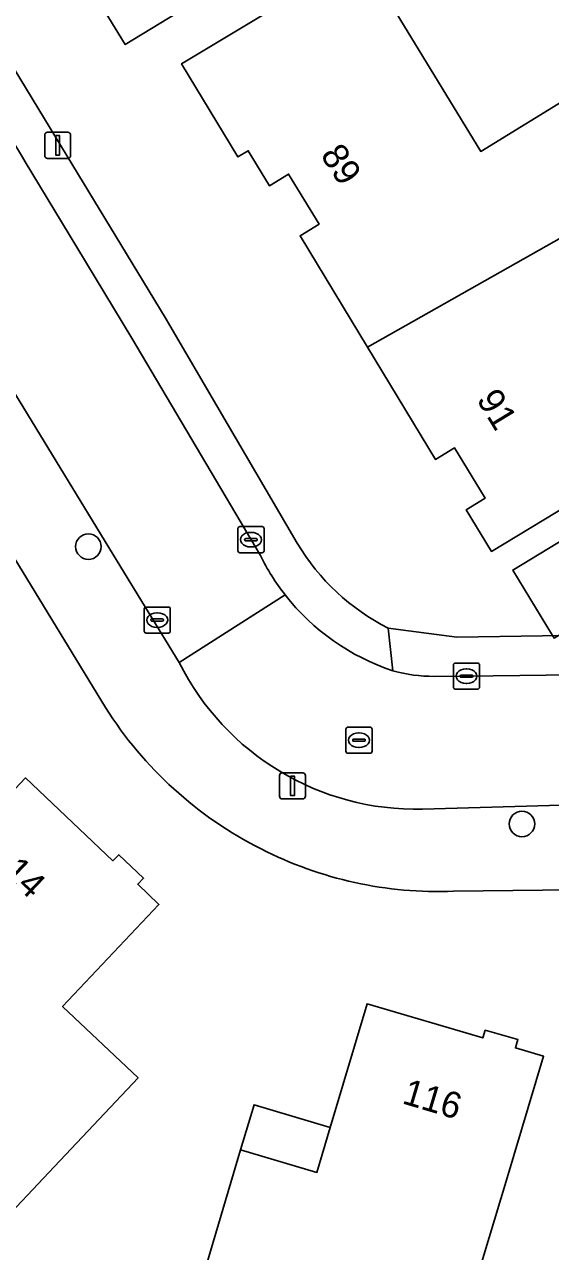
# Model space of a CAD drawing. Extents: x 157767 to 159172, y 387839 to 389425.
# Drawn here: x 158070.43 to 158090.6, y 388608.77 to 388655.84 of the extents above; entities that cross this region are included whole.
import ezdxf

# ---------------------------------------------------------------- set-up
doc = ezdxf.new("R2010")
doc.units = 0
for name, color, linetype in [('IMGEO_Boom', 7, 'Continuous'), ('IMGEO_Erf', 7, 'Continuous'), ('IMGEO_Kolk', 7, 'Continuous'), ('IMGEO_Lichtmast', 7, 'Continuous'), ('IMGEO_Muur', 7, 'Continuous'), ('IMGEO_Pand', 7, 'Continuous'), ('IMGEO_Pand_nummerreeks', 7, 'Continuous'), ('IMGEO_Pand_overbouw', 7, 'Continuous'), ('IMGEO_Rijbaan_lokaal_open', 7, 'Continuous'), ('IMGEO_Rioolput', 7, 'Continuous'), ('IMGEO_Voetpad_open', 7, 'Continuous')]:
    doc.layers.add(name, color=color, linetype=linetype)

msp = doc.modelspace()

# ---------------------------------------------------------------- linework, layer by layer
at = {"layer": 'IMGEO_Boom'}
for centre in [(158072.879, 388635.811), (158089.511, 388625.171)]:
    msp.add_circle(centre, 0.489, dxfattribs=at)
at = {"layer": 'IMGEO_Erf'}
for points in [[(158084.381, 388632.682), (158087.009, 388632.342), (158090.303, 388632.39), (158090.684, 388632.396), (158089.16, 388634.912), (158092.905, 388637.179), (158094.487, 388634.565), (158090.907, 388632.399), (158106.724, 388632.63), (158109.87, 388633.38), (158113.99, 388634.449), (158158.26, 388653.682), (158159.32, 388658.046), (158157.478, 388662.318), (158148.912, 388682.181)], [(158068.943, 388680.157), (158069.57, 388679.146), (158073.821, 388681.779), (158076.455, 388677.529), (158077.139, 388676.424), (158076.034, 388675.74), (158077.06, 388674.085), (158076.816, 388673.284), (158073.526, 388671.246), (158069.275, 388668.613), (158067.496, 388671.486), (158066.81, 388671.062), (158064.973, 388674.028), (158063.613, 388673.186), (158061.971, 388675.839), (158058.217, 388673.595), (158071.632, 388651.501), (158075.819, 388644.604), (158080.893, 388635.943)], [(158083.337, 388658.496), (158087.93, 388650.973), (158091.558, 388653.188), (158091.001, 388654.102), (158102.334, 388660.865)], [(158104.332, 388656.326), (158104.729, 388655.423), (158111.688, 388639.608), (158113.703, 388635.032), (158109.87, 388633.38), (158104.612, 388645.469), (158098.492, 388641.767), (158094.852, 388639.565), (158088.341, 388635.625), (158087.374, 388637.223), (158088.105, 388637.669), (158086.922, 388639.602), (158086.191, 388639.155), (158083.585, 388643.461), (158080.998, 388647.735), (158081.729, 388648.183), (158080.555, 388650.099), (158079.825, 388649.652), (158079.012, 388650.995), (158078.617, 388650.757), (158076.454, 388654.33), (158080.732, 388656.919)], [(158073.538, 388629.633), (158065.111, 388643.432), (158048.605, 388633.424), (158041.934, 388629.381), (158019.422, 388615.682), (158006.062, 388607.391), (158003.544, 388605.795), (158007.121, 388599.66), (158008.464, 388601.21), (158008.786, 388601.467), (158010.188, 388602.586), (158011.828, 388603.703), (158014.005, 388604.812), (158016.147, 388601.216), (158027.188, 388581.174), (158029.267, 388577.665), (158033.868, 388570.534), (158041.859, 388557.406), (158043.338, 388554.813), (158043.765, 388552.918), (158061.703, 388519.687), (158072.331, 388500), (158089.66, 388467.898), (158102.446, 388447.213)], [(158071.868, 388569.477), (158073.688, 388570.574), (158071.294, 388574.467), (158070.805, 388574.17), (158064.549, 388584.468), (158067.954, 388586.536), (158074.21, 388576.238), (158073.945, 388576.077), (158076.333, 388572.168), (158077.663, 388572.97), (158080.097, 388569.003), (158089.644, 388574.957), (158091.518, 388574.404), (158095.729, 388573.163), (158096.009, 388573.979), (158110.825, 388622.857), (158086.888, 388622.589)]]:
    msp.add_lwpolyline(points, dxfattribs=at)
for points in [[(158082.273, 388659.064), (158078.01, 388656.45), (158077.608, 388657.105), (158074.29, 388655.07), (158070.739, 388660.892), (158073.774, 388662.748), (158073.844, 388662.791), (158072.064, 388665.703), (158073.306, 388666.463), (158077.571, 388669.073), (158079.175, 388670.054), (158082.201, 388665.117), (158084.917, 388660.685), (158082.61, 388659.27)], [(158067.64, 388611.59), (158067.598, 388613.613), (158068.491, 388614.561), (158065.977, 388616.929), (158062.894, 388613.658), (158058.049, 388618.224), (158060.19, 388620.454), (158063.653, 388624.06), (158065.8, 388621.999), (158067.059, 388623.331), (158070.47, 388626.939), (158073.821, 388623.759), (158074.041, 388623.991), (158074.994, 388623.089), (158074.774, 388622.857), (158075.586, 388622.087), (158071.89, 388618.165), (158074.785, 388615.436), (158071.356, 388611.798), (158069.503, 388609.833)], [(158076.409, 388604.909), (158077.293, 388607.881), (158078.719, 388612.673), (158081.643, 388611.804), (158082.157, 388613.529), (158083.569, 388618.273), (158088.009, 388616.965), (158088.103, 388617.258), (158089.358, 388616.898), (158089.258, 388616.577), (158090.34, 388616.259), (158088.902, 388611.471), (158087.362, 388606.343), (158082.858, 388607.684), (158081.574, 388603.371)]]:
    msp.add_lwpolyline(points, close=True, dxfattribs=at)
for centre, radius, start, end in [((158088.222, 388640.286), 8.519, 210.6516, 243.2012), ((158086.295, 388637.686), 15.086, 212.2641, 243.2736), ((158086.302, 388637.506), 14.928, 242.9373, 272.2503)]:
    msp.add_arc(centre, radius, start, end, dxfattribs=at)
at = {"layer": 'IMGEO_Kolk'}
for p, q in [((158078.614, 388635.651), (158078.614, 388636.503)), ((158078.689, 388636.577), (158079.541, 388636.577)), ((158079.102, 388636.357), (158079.127, 388636.357)), ((158079.615, 388636.503), (158079.615, 388635.651)), ((158078.873, 388636.071), (158078.873, 388636.083)), ((158079.311, 388636.034), (158078.913, 388636.034)), ((158078.916, 388636.12), (158079.314, 388636.12)), ((158079.357, 388636.083), (158079.357, 388636.071)), ((158079.541, 388635.577), (158078.689, 388635.577)), ((158079.125, 388635.797), (158079.1, 388635.797)), ((158075.093, 388633.491), (158075.945, 388633.491)), ((158075.018, 388632.565), (158075.018, 388633.417)), ((158075.32, 388633.034), (158075.718, 388633.034)), ((158075.506, 388633.271), (158075.531, 388633.271)), ((158076.019, 388633.417), (158076.019, 388632.565)), ((158075.277, 388632.985), (158075.277, 388632.997)), ((158075.715, 388632.948), (158075.317, 388632.948)), ((158075.529, 388632.711), (158075.504, 388632.711)), ((158075.761, 388632.997), (158075.761, 388632.985)), ((158075.945, 388632.491), (158075.093, 388632.491)), ((158086.881, 388630.416), (158086.881, 388631.268)), ((158086.956, 388631.342), (158087.808, 388631.342)), ((158087.369, 388631.122), (158087.394, 388631.122)), ((158087.882, 388631.268), (158087.882, 388630.416)), ((158087.14, 388630.836), (158087.14, 388630.848)), ((158087.578, 388630.799), (158087.18, 388630.799)), ((158087.183, 388630.885), (158087.581, 388630.885)), ((158087.624, 388630.848), (158087.624, 388630.836)), ((158087.808, 388630.342), (158086.956, 388630.342)), ((158087.392, 388630.562), (158087.367, 388630.562))]:
    msp.add_line(p, q, dxfattribs=at)
for points in [[(158078.614, 388635.651), (158078.614, 388636.503)], [(158078.689, 388636.577), (158079.541, 388636.577)], [(158079.615, 388636.503), (158079.615, 388635.651)], [(158079.541, 388635.577), (158078.689, 388635.577)], [(158075.093, 388633.491), (158075.945, 388633.491)], [(158075.018, 388632.565), (158075.018, 388633.417)], [(158076.019, 388633.417), (158076.019, 388632.565)], [(158075.945, 388632.491), (158075.093, 388632.491)], [(158086.881, 388630.416), (158086.881, 388631.268)], [(158086.956, 388631.342), (158087.808, 388631.342)], [(158087.882, 388631.268), (158087.882, 388630.416)], [(158087.808, 388630.342), (158086.956, 388630.342)]]:
    msp.add_lwpolyline(points, dxfattribs=at)
for centre, radius, start, end in [((158078.691, 388636.501), 0.0765, 91.552, 178.448), ((158078.691, 388636.501), 0.0765, 91.552, 178.448), ((158079.539, 388636.501), 0.0765, 1.552, 88.448), ((158079.539, 388636.501), 0.0765, 1.552, 88.448), ((158078.913, 388636.08), 0.0403, 85.8775, 175.7526), ((158078.91, 388636.07), 0.0366, 178.938, 274.7102), ((158079.314, 388636.077), 0.043, 264.8664, 352.4533), ((158079.318, 388636.082), 0.0386, 1.7309, 96.639), ((158078.691, 388635.653), 0.0765, 181.552, 268.448), ((158078.691, 388635.653), 0.0765, 181.552, 268.448), ((158079.539, 388635.653), 0.0765, 271.552, 358.448), ((158079.539, 388635.653), 0.0765, 271.552, 358.448), ((158075.095, 388633.415), 0.0765, 91.552, 178.448), ((158075.095, 388633.415), 0.0765, 91.552, 178.448), ((158075.943, 388633.415), 0.0765, 1.552, 88.448), ((158075.943, 388633.415), 0.0765, 1.552, 88.448), ((158075.317, 388632.994), 0.0403, 85.8775, 175.7526), ((158075.722, 388632.996), 0.0386, 1.7309, 96.639), ((158075.095, 388632.567), 0.0765, 181.552, 268.448), ((158075.095, 388632.567), 0.0765, 181.552, 268.448), ((158075.314, 388632.984), 0.0366, 178.938, 274.7102), ((158075.718, 388632.991), 0.043, 264.8664, 352.4533), ((158075.943, 388632.567), 0.0765, 271.552, 358.448), ((158075.943, 388632.567), 0.0765, 271.552, 358.448), ((158086.958, 388631.266), 0.0765, 91.552, 178.448), ((158086.958, 388631.266), 0.0765, 91.552, 178.448), ((158087.806, 388631.266), 0.0765, 1.552, 88.448), ((158087.806, 388631.266), 0.0765, 1.552, 88.448), ((158087.18, 388630.845), 0.0403, 85.8775, 175.7526), ((158087.177, 388630.835), 0.0366, 178.938, 274.7102), ((158087.581, 388630.842), 0.043, 264.8664, 352.4533), ((158087.585, 388630.847), 0.0386, 1.7309, 96.639), ((158086.958, 388630.418), 0.0765, 181.552, 268.448), ((158086.958, 388630.418), 0.0765, 181.552, 268.448), ((158087.806, 388630.418), 0.0765, 271.552, 358.448), ((158087.806, 388630.418), 0.0765, 271.552, 358.448)]:
    msp.add_arc(centre, radius, start, end, dxfattribs=at)
for centre, major_axis, ratio, start_param, end_param in [((158079.101, 388636.077), (-0.387, 0.002), 0.722429, 4.712389, 7.853982), ((158079.126, 388636.077), (-0.39, 0.002), 0.717154, 1.570796, 4.712389), ((158075.505, 388632.991), (-0.387, 0.002), 0.722429, 4.712389, 7.853982), ((158075.53, 388632.991), (-0.39, 0.002), 0.717154, 1.570796, 4.712389), ((158087.368, 388630.842), (-0.387, 0.002), 0.722429, 4.712389, 7.853982), ((158087.393, 388630.842), (-0.39, 0.002), 0.717154, 1.570796, 4.712389)]:
    msp.add_ellipse(centre, major_axis=major_axis, ratio=ratio, start_param=start_param, end_param=end_param, dxfattribs=at)
at = {"layer": 'IMGEO_Lichtmast'}
for p, q in [((158071.205, 388650.803), (158071.205, 388651.603)), ((158071.205, 388651.603), (158071.205, 388650.803)), ((158071.305, 388651.703), (158072.095, 388651.703)), ((158072.095, 388651.703), (158071.305, 388651.703)), ((158072.195, 388651.603), (158072.195, 388650.803)), ((158072.195, 388650.803), (158072.195, 388651.603)), ((158072.095, 388650.703), (158071.305, 388650.703)), ((158071.305, 388650.703), (158072.095, 388650.703)), ((158080.212, 388626.233), (158080.212, 388627.033)), ((158080.212, 388627.033), (158080.212, 388626.233)), ((158080.312, 388627.133), (158081.102, 388627.133)), ((158081.102, 388627.133), (158080.312, 388627.133)), ((158081.202, 388627.033), (158081.202, 388626.233)), ((158081.202, 388626.233), (158081.202, 388627.033)), ((158081.102, 388626.133), (158080.312, 388626.133)), ((158080.312, 388626.133), (158081.102, 388626.133))]:
    msp.add_line(p, q, dxfattribs=at)
for points in [[(158071.625, 388651.578), (158071.775, 388651.578), (158071.775, 388650.828), (158071.625, 388650.828), (158071.625, 388651.578)], [(158080.632, 388627.008), (158080.782, 388627.008), (158080.782, 388626.258), (158080.632, 388626.258), (158080.632, 388627.008)]]:
    msp.add_lwpolyline(points, dxfattribs=at)
for centre, start, end in [((158071.305, 388651.603), 90, 180), ((158071.305, 388651.603), 90, 180), ((158072.095, 388651.603), 0, 90), ((158072.095, 388651.603), 360, 90), ((158071.305, 388650.803), 180, 270), ((158071.305, 388650.803), 180, 270), ((158072.095, 388650.803), 270, 0), ((158072.095, 388650.803), 270, 0), ((158080.312, 388627.033), 90, 180), ((158080.312, 388627.033), 90, 180), ((158081.102, 388627.033), 0, 90), ((158081.102, 388627.033), 360, 90), ((158080.312, 388626.233), 180, 270), ((158080.312, 388626.233), 180, 270), ((158081.102, 388626.233), 270, 0), ((158081.102, 388626.233), 270, 0)]:
    msp.add_arc(centre, 0.1, start, end, dxfattribs=at)
at = {"layer": 'IMGEO_Muur'}
msp.add_lwpolyline([(158109.87, 388633.38), (158106.724, 388632.63), (158090.303, 388632.39)], dxfattribs=at)
at = {"layer": 'IMGEO_Pand'}
for points in [[(158082.201, 388665.117), (158079.175, 388670.054), (158077.571, 388669.073), (158073.306, 388666.463), (158072.064, 388665.703), (158073.844, 388662.791), (158073.774, 388662.748), (158070.739, 388660.892), (158074.29, 388655.07), (158077.608, 388657.105), (158078.01, 388656.45), (158082.273, 388659.064), (158082.61, 388659.27), (158084.917, 388660.685)], [(158083.337, 388658.496), (158080.732, 388656.919), (158076.454, 388654.33), (158078.617, 388650.757), (158079.012, 388650.995), (158079.825, 388649.652), (158080.555, 388650.099), (158081.729, 388648.183), (158080.998, 388647.735), (158083.585, 388643.461), (158104.729, 388655.423), (158104.332, 388656.326), (158102.334, 388660.865), (158091.001, 388654.102), (158091.558, 388653.188), (158087.93, 388650.973)], [(158098.492, 388641.767), (158104.612, 388645.469), (158109.87, 388633.38), (158113.703, 388635.032), (158111.688, 388639.608), (158104.729, 388655.423), (158083.585, 388643.461), (158086.191, 388639.155), (158086.922, 388639.602), (158088.105, 388637.669), (158087.374, 388637.223), (158088.341, 388635.625), (158094.852, 388639.565)], [(158089.16, 388634.912), (158090.684, 388632.396), (158090.742, 388632.299), (158090.907, 388632.399), (158094.487, 388634.565), (158092.905, 388637.179)], [(158068.491, 388614.561), (158067.598, 388613.613), (158067.64, 388611.59), (158069.503, 388609.833), (158071.356, 388611.798), (158074.785, 388615.436), (158071.89, 388618.165), (158075.586, 388622.087), (158074.774, 388622.857), (158074.994, 388623.089), (158074.041, 388623.991), (158073.821, 388623.759), (158070.47, 388626.939), (158067.059, 388623.331), (158065.8, 388621.999), (158063.653, 388624.06), (158060.19, 388620.454), (158058.049, 388618.224), (158062.894, 388613.658), (158065.977, 388616.929)], [(158078.719, 388612.673), (158077.293, 388607.881), (158076.409, 388604.909), (158081.574, 388603.371), (158082.858, 388607.684), (158087.362, 388606.343), (158088.902, 388611.471), (158090.34, 388616.259), (158089.258, 388616.577), (158089.358, 388616.898), (158088.103, 388617.258), (158088.009, 388616.965), (158083.569, 388618.273), (158082.157, 388613.529), (158081.643, 388611.804)]]:
    msp.add_lwpolyline(points, close=True, dxfattribs=at)
at = {"layer": 'IMGEO_Pand_overbouw'}
msp.add_lwpolyline([(158078.719, 388612.673), (158081.643, 388611.804), (158082.157, 388613.529), (158079.233, 388614.398)], close=True, dxfattribs=at)
at = {"layer": 'IMGEO_Rijbaan_lokaal_open'}
for points in [[(158079.479, 388635.466), (158074.539, 388643.81), (158072.431, 388647.303), (158070.457, 388650.573), (158070.352, 388650.747), (158069.575, 388652.039), (158066.309, 388657.375), (158061.493, 388665.301), (158055.506, 388675.171), (158053.536, 388678.444), (158051.319, 388682.056)], [(158047.465, 388678.857), (158049.671, 388675.314), (158053.554, 388668.935), (158066.288, 388647.922), (158067.854, 388645.332), (158068.111, 388644.907), (158070.083, 388641.645), (158073.98, 388635.256), (158076.366, 388631.359), (158080.427, 388633.957)], [(158080.427, 388633.957), (158076.366, 388631.359)], [(158110.861, 388631.14), (158087.378, 388630.841), (158086.143, 388630.833)], [(158085.699, 388625.739), (158091.452, 388625.907), (158097.745, 388626.013), (158101.53, 388626.077), (158110.492, 388626.173)]]:
    msp.add_lwpolyline(points, dxfattribs=at)
for centre, radius, start, end in [((158087.369, 388639.37), 8.803, 206.329, 217.9476), ((158087.31, 388639.342), 8.739, 218.037, 251.6727), ((158085.464, 388635.908), 10.172, 206.5663, 271.324), ((158086.107, 388636.541), 5.708, 254.2945, 270.3596)]:
    msp.add_arc(centre, radius, start, end, dxfattribs=at)
at = {"layer": 'IMGEO_Rioolput'}
for p, q in [((158082.758, 388627.958), (158082.758, 388628.81)), ((158082.833, 388628.884), (158083.685, 388628.884)), ((158083.759, 388628.81), (158083.759, 388627.958)), ((158083.017, 388628.378), (158083.017, 388628.39)), ((158083.455, 388628.341), (158083.057, 388628.341)), ((158083.06, 388628.427), (158083.458, 388628.427)), ((158083.246, 388628.664), (158083.271, 388628.664)), ((158083.501, 388628.39), (158083.501, 388628.378)), ((158083.685, 388627.884), (158082.833, 388627.884)), ((158083.269, 388628.104), (158083.244, 388628.104))]:
    msp.add_line(p, q, dxfattribs=at)
for points in [[(158082.758, 388627.958), (158082.758, 388628.81)], [(158082.833, 388628.884), (158083.685, 388628.884)], [(158083.759, 388628.81), (158083.759, 388627.958)], [(158083.685, 388627.884), (158082.833, 388627.884)]]:
    msp.add_lwpolyline(points, dxfattribs=at)
for centre, radius, start, end in [((158082.835, 388628.808), 0.0765, 91.552, 178.448), ((158082.835, 388628.808), 0.0765, 91.552, 178.448), ((158083.683, 388628.808), 0.0765, 1.552, 88.448), ((158083.683, 388628.808), 0.0765, 1.552, 88.448), ((158083.057, 388628.387), 0.0403, 85.8775, 175.7526), ((158083.054, 388628.377), 0.0366, 178.938, 274.7102), ((158083.458, 388628.384), 0.043, 264.8664, 352.4533), ((158083.462, 388628.389), 0.0386, 1.7309, 96.639), ((158082.835, 388627.96), 0.0765, 181.552, 268.448), ((158082.835, 388627.96), 0.0765, 181.552, 268.448), ((158083.683, 388627.96), 0.0765, 271.552, 358.448), ((158083.683, 388627.96), 0.0765, 271.552, 358.448)]:
    msp.add_arc(centre, radius, start, end, dxfattribs=at)
for centre, major_axis, ratio, start_param, end_param in [((158083.245, 388628.384), (-0.387, 0.002), 0.722429, 4.712389, 7.853982), ((158083.27, 388628.384), (-0.39, 0.002), 0.717154, 1.570796, 4.712389)]:
    msp.add_ellipse(centre, major_axis=major_axis, ratio=ratio, start_param=start_param, end_param=end_param, dxfattribs=at)
at = {"layer": 'IMGEO_Voetpad_open'}
for points in [[(158297.552, 388713.441), (158293.914, 388712.06), (158281.335, 388706.644), (158265.791, 388699.949), (158226.572, 388683.059), (158223.84, 388681.871), (158171.568, 388659.372), (158166.983, 388658.516), (158164.943, 388657.643), (158162.824, 388656.737), (158158.26, 388653.682), (158113.99, 388634.449), (158109.87, 388633.38), (158106.724, 388632.63), (158090.907, 388632.399), (158090.742, 388632.299), (158090.684, 388632.396), (158090.303, 388632.39), (158087.009, 388632.342), (158084.381, 388632.682), (158084.562, 388631.046)], [(158080.893, 388635.943), (158075.819, 388644.604), (158071.632, 388651.501), (158058.217, 388673.595), (158056.692, 388676.089), (158052.773, 388682.571)], [(158051.319, 388682.056), (158053.536, 388678.444), (158055.506, 388675.171), (158061.493, 388665.301), (158066.309, 388657.375), (158069.575, 388652.039), (158070.352, 388650.747), (158070.457, 388650.573), (158072.431, 388647.303), (158074.539, 388643.81), (158079.479, 388635.466)], [(158076.366, 388631.359), (158073.98, 388635.256), (158070.083, 388641.645), (158068.111, 388644.907), (158067.854, 388645.332), (158067.431, 388645.075), (158065.111, 388643.432), (158073.538, 388629.633)], [(158084.562, 388631.046), (158084.381, 388632.682)], [(158086.143, 388630.833), (158087.378, 388630.841), (158110.861, 388631.14)], [(158110.492, 388626.173), (158101.53, 388626.077), (158097.745, 388626.013), (158091.452, 388625.907), (158085.699, 388625.739)], [(158086.888, 388622.589), (158110.825, 388622.857), (158112.707, 388622.305)]]:
    msp.add_lwpolyline(points, dxfattribs=at)
for centre, radius, start, end in [((158088.222, 388640.286), 8.519, 210.6516, 243.2012), ((158087.369, 388639.37), 8.803, 206.329, 217.9476), ((158087.31, 388639.342), 8.739, 218.037, 251.6727), ((158085.464, 388635.908), 10.172, 206.5663, 271.324), ((158086.107, 388636.541), 5.708, 254.2945, 270.3596), ((158086.295, 388637.686), 15.086, 212.2641, 243.2736), ((158086.302, 388637.506), 14.928, 242.9373, 272.2503)]:
    msp.add_arc(centre, radius, start, end, dxfattribs=at)

# ---------------------------------------------------------------- texts
at = {"layer": 'IMGEO_Pand_nummerreeks'}
for s, rotation, p in [('89', 303.323, (158081.756, 388650.83)), ('91', 301.2546, (158087.747, 388641.46)), ('114', 316.4998, (158069.02, 388623.792)), ('116', 343.4352, (158084.874, 388614.463))]:
    msp.add_text(s, height=1, rotation=rotation, dxfattribs=at).set_placement(p)

doc.saveas('drawing.dxf')
